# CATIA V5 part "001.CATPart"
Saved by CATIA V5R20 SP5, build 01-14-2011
Part number: Part2
Material "Flint": density 2690 kg/m3
Material "Light Green": density 7860 kg/m3, Young's modulus 2e+11 Pa, Poisson ratio 0.266
Bounding box of the stored display mesh (mm): x -25 to 25, y -25 to 25, z 0 to 110
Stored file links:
  E:\001.CATPart
  C:\Program Files\Dassault Systemes\B20\intel_a\startup\materials\Catalog.CATMaterial
  C:\Program Files\Dassault Systemes\B20\intel_a\startup\materials\flint.jpg
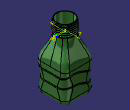
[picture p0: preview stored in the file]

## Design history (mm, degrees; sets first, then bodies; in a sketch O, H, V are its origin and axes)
Set1, material "Flint"
  Sketch1 on xy-plane, origin (0, 0, 0), H (1, 0, 0), V (0, 1, 0)
    line L1 (25, 25) -> (25, -25)
    line L2 (25, -25) -> (-25, -25)
    line L3 (-25, -25) -> (-25, 25)
    line L4 (-25, 25) -> (25, 25)
    length L4 = 50
    length L1 = 50
    vertical: L1 V, L3 V
    horizontal: L2 H, L4 H
    equidistance: L1 L3 O, L2 L4 O
  Sketch2 on face of Pad1 from Sketch1.L2, origin (0, -25, 0), H (1, 0, 0), V (0, 0, 1)
    spline S1 through (-43.2501, 26.4653) (-13.1681, 19.9968) (0, 24.7012) (12.5884, 26.4653) (42.4738, 18.4287) (51.9113, 12.9403)
    point P1 (0, 24.7012)
    coincidence: P1 V
  Extrude1: Element1 Sketch2, Lim1 60, Lim2 60
  MultiSel1: CommonCtxFeats ({extract ExtractElem face of Pad1 from Sketch1.L2}; {extract ExtractElem face of Fillet1}; {extract ExtractElem face of Pad1 from Sketch1.L1}; {extract ExtractElem face of Fillet1}; {extract ExtractElem face of Pad1 from Sketch1.L4}; {extract ExtractElem face of Fillet1}; {extract ExtractElem face of Pad1 from Sketch1.L3}; {extract ExtractElem face of Fillet1})
  Sketch3 on face of Pad1 from Sketch1.L4, origin (0, 25, 0), H (-1, 0, 0), V (0, 0, 1)
    spline S1 through (-33.2157, 35.8347) (0, 42.1703) (36.346, 28.9853) (44.4186, 28.9853)
    point P1 (0, 42.1703)
    coincidence: P1 V
  Extrude2: Element1 Sketch3, Lim1 60, Lim2 60
  MultiSel2: CommonCtxFeats ({extract ExtractElem face of Fillet1}; {extract ExtractElem face of Pad1 from Sketch1.L1}; {extract ExtractElem face of Fillet1}; {extract ExtractElem face of Pad1 from Sketch1.L4}; {extract ExtractElem face of Fillet1}; {extract ExtractElem face of Pad1 from Sketch1.L3}; {extract ExtractElem face of Fillet1}; {extract ExtractElem face of Pad1 from Sketch1.L2})
  Join1: Elements ({intersect ToIntersect1 {extract ExtractElem face of Pad1 from Sketch1.L2}, ToIntersect2 Extrude1}; {intersect ToIntersect1 {extract ExtractElem face of Fillet1}, ToIntersect2 Extrude1}; {intersect ToIntersect1 {extract ExtractElem face of Pad1 from Sketch1.L1}, ToIntersect2 Extrude1}; {intersect ToIntersect1 {extract ExtractElem face of Fillet1}, ToIntersect2 Extrude1}; {intersect ToIntersect1 {extract ExtractElem face of Pad1 from Sketch1.L4}, ToIntersect2 Extrude1}; {intersect ToIntersect1 {extract ExtractElem face of Fillet1}, ToIntersect2 Extrude1}; {intersect ToIntersect1 {extract ExtractElem face of Pad1 from Sketch1.L3}, ToIntersect2 Extrude1}; {intersect ToIntersect1 {extract ExtractElem face of Fillet1}, ToIntersect2 Extrude1})
  Join2: Elements ({intersect ToIntersect1 {extract ExtractElem face of Fillet1}, ToIntersect2 Extrude2}; {intersect ToIntersect1 {extract ExtractElem face of Pad1 from Sketch1.L1}, ToIntersect2 Extrude2}; {intersect ToIntersect1 {extract ExtractElem face of Fillet1}, ToIntersect2 Extrude2}; {intersect ToIntersect1 {extract ExtractElem face of Pad1 from Sketch1.L4}, ToIntersect2 Extrude2}; {intersect ToIntersect1 {extract ExtractElem face of Fillet1}, ToIntersect2 Extrude2}; {intersect ToIntersect1 {extract ExtractElem face of Pad1 from Sketch1.L3}, ToIntersect2 Extrude2}; {intersect ToIntersect1 {extract ExtractElem face of Fillet1}, ToIntersect2 Extrude2}; {intersect ToIntersect1 {extract ExtractElem face of Pad1 from Sketch1.L2}, ToIntersect2 Extrude2})
  Plane1: type Normal, Curve edge of MultiSel2, RefPoint vertex [face of MultiSel2 | face of MultiSel2]
  Plane2: type Normal, Curve Join1, RefPoint vertex [face of MultiSel1 | face of MultiSel1]
  Circle1: type CtrRad, Start 0, End 180, Center vertex [face of MultiSel2 | face of MultiSel2], Support Plane1, Radius 1, FirstDirection (-1, 0, 0)
  Circle2: type CtrRad, Start 0, End 180, Center vertex [face of MultiSel1 | face of MultiSel1], Support Plane2, Radius 1, FirstDirection (-1, 0, 0)
Body1 (main body), material "Light Green"
  Pad1: profile Sketch1, direction (0, 0, 1), length 50
  Fillet1: on edge [face of Pad1 from Sketch1.L3 | face of Pad1 from Sketch1.L4]; edge [face of Pad1 from Sketch1.L2 | face of Pad1 from Sketch1.L3]; edge [face of Pad1 from Sketch1.L4 | face of Pad1 from Sketch1.L1]; edge [face of Pad1 from Sketch1.L1 | face of Pad1 from Sketch1.L2]
  Plane3: type Offset, RefPlane xy-plane, Offset 50
  Plane4: type Offset, RefPlane Plane3, Offset 40
  Fillet2: on edge [start face of Pad1 | face of Pad1 from Sketch1.L1]
  Sketch4 on Plane4, origin (0, 0, 90), H (1, 0, 0), V (0, 1, 0)
    circle A1 centre (0, 0) radius 15
  Pad2: profile Sketch4, direction (0, 0, 1), length 20
  Sketch5 on start face of Pad2, origin (0, 0, 90), H (1, 0, 0), V (0, -1, 0)
    point P1 (15, 0)
    distance V P1 = 15
    coincidence: P1 H
  Sketch6 on end face of Pad1, origin (0, 0, 50), H (1, 0, 0), V (0, 1, 0)
    point P1 (25, 0)
    distance V P1 = 25
  Loft1: solid, Sections ({boundary Boundary {extract ExtractElem end face of Pad1}}; {boundary Boundary {extract ExtractElem start face of Pad2}}), StartFace end face of Pad1, EndFace start face of Pad2
  Slot1: profile Circle1, centre curve Join2
  Slot2: profile Circle2, centre curve Join1
  Shell1: ExtOffset 0, Face end face of Pad2, IntOffset 1
  Plane5: type Offset, RefPlane Plane4, Offset 2
  Sketch7 on Plane5, origin (0, 0, 92), H (1, 0, 0), V (0, 1, 0)
    point P1 (15, 0)
    distance V P1 = 15
    coincidence: P1 H
  Helix1: Direction Z axis, RefPoint Sketch7, Pitch 3, Height 16, TaperAngle 0
  Point1: type OnCurve, Support Helix1, Length 5
  Line1: type PtDir, RefPoint Sketch7, Direction (1, 0, 0), Start 0, End 5
  Connect1: Curve1 Line1, Point1 vertex of Line1, Tension1 1, Curve2 Helix1, Point2 Point1, Tension2 1
  Point2: type OnCurve, Support Connect1, RefPoint vertex of Helix1, Length 5
  Line2: type PtDir, RefPoint vertex of Helix1, Direction (0, 1, 0), Start 0, End 5
  Connect2: Curve1 Line2, Point1 vertex of Line2, Tension1 1, Curve2 Connect1, Point2 Point2, Tension2 1
  Plane6: type Normal, Curve Connect2
  Sketch8 on Plane6, origin (2.8332, -1.4456, 0.1012), H (-0.4545, -0.8908, 0), V (-0.0283, 0.0145, 0.9995)
    circle A1 centre (14.9812, 100.0128) radius 1
  Rib1: profile Sketch8, centre curve Connect2
  Sketch9 on Plane4, origin (0, 0, 90), H (1, 0, 0), V (0, 1, 0)
    circle A1 centre (0, 0) radius 14
  Body2
    Sketch10 on Plane4, origin (0, 0, 90), H (1, 0, 0), V (0, 1, 0)
      circle A1 centre (0, 0) radius 14
      point P1 (14, 0)
      coincidence: A1 P1, P1 H
    Pad3: profile Sketch10, direction (0, 0, 1), length 20
  Remove1: tool Body2
Body3
  Sketch11 on face of Pad1 from Sketch1.L3, origin (-25, 0, 0), H (0, -1, 0), V (0, 0, 1)
    polyline C1
    polyline C2
    polyline C3
    polyline C4
    polyline C5
    polyline C6
    polyline C7
    polyline C8
    polyline C9
    polyline C10
    polyline C11
  Pocket1: profile Sketch11, direction (1, 0, 0), length 0.5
